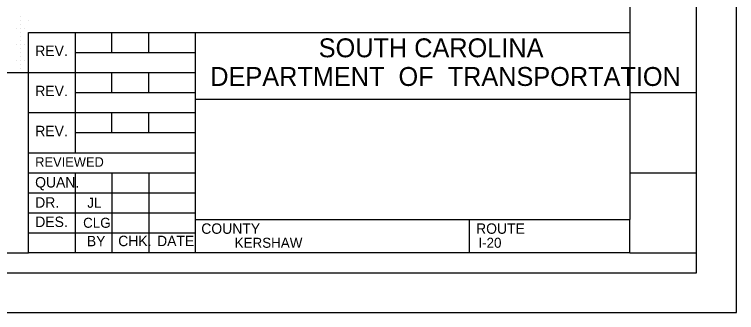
# Model space of a CAD drawing. Extents: x -1.4 to 34.6, y 0.5 to 22.5.
# Drawn here: x 25.59 to 34.6, y 0.5 to 4.22 of the extents above; entities that cross this region are included whole.
import ezdxf

# ---------------------------------------------------------------- set-up
doc = ezdxf.new("R2010")
doc.units = 0
for name, color, linetype in [('BR_BORDER LINES', 7, 'Continuous'), ('BR_GRID DOTS', 7, 'Continuous'), ('BR_GRID LINES', 7, 'Continuous'), ('BR_TEXT', 7, 'Continuous'), ('RD_SHT_IplotShp', 7, 'Continuous')]:
    doc.layers.add(name, color=color, linetype=linetype)

msp = doc.modelspace()

# ---------------------------------------------------------------- linework, layer by layer
at = {"layer": 'BR_BORDER LINES'}
for p, q in [((34.097, 0.993), (34.097, 21.9962)), ((33.2637, 11.2429), (33.2637, 4.043)), ((25.7637, 1.243), (25.7637, 3.993)), ((25.7637, 3.993), (33.2637, 3.993)), ((26.347, 3.993), (26.347, 2.493)), ((26.8054, 3.743), (26.8054, 3.993)), ((27.2637, 3.743), (27.2637, 3.993)), ((27.847, 1.243), (27.847, 3.993)), ((33.2637, 4.043), (33.2637, 1.6597)), ((26.347, 3.743), (27.847, 3.743)), ((23.4512, 3.493), (25.7637, 3.493)), ((25.7637, 3.493), (27.847, 3.493)), ((26.8054, 3.243), (26.8054, 3.493)), ((27.2637, 3.243), (27.2637, 3.493)), ((26.347, 3.243), (27.847, 3.243)), ((27.847, 3.1597), (33.2637, 3.1597)), ((27.847, 3.1597), (27.847, 3.1597)), ((33.2637, 3.1597), (33.2637, 3.1597)), ((25.7637, 2.993), (27.847, 2.993)), ((26.8054, 2.743), (26.8054, 2.993)), ((27.2637, 2.743), (27.2637, 2.993)), ((26.347, 2.743), (27.847, 2.743)), ((25.7637, 2.493), (27.847, 2.493)), ((25.7637, 2.243), (27.847, 2.243)), ((26.347, 2.243), (26.347, 1.243)), ((26.8054, 2.243), (26.8054, 1.243)), ((27.2637, 2.243), (27.2637, 1.243)), ((25.7637, 1.993), (27.847, 1.993)), ((25.7637, 1.743), (27.847, 1.743)), ((27.847, 1.6597), (33.2637, 1.6597)), ((31.2637, 1.243), (31.2637, 1.6597)), ((33.2637, 1.243), (33.2637, 1.6597)), ((25.7637, 1.493), (27.847, 1.493)), ((1.264, 1.243), (25.7638, 1.243)), ((33.2637, 1.243), (25.7638, 1.243)), ((0.4307, 0.993), (34.097, 0.993))]:
    msp.add_line(p, q, dxfattribs=at)
at = {"layer": 'BR_GRID DOTS'}
for p, q in [((25.6638, 4.193), (25.6638, 4.193)), ((25.6638, 4.143), (25.6638, 4.143)), ((25.6638, 4.093), (25.6638, 4.093)), ((25.6638, 4.093), (25.6638, 4.093)), ((25.7638, 4.143), (25.7638, 4.143)), ((25.6138, 4.043), (25.6138, 4.043)), ((25.6638, 4.043), (25.6638, 4.043)), ((25.6638, 3.993), (25.6638, 3.993)), ((25.7138, 4.043), (25.7138, 4.043)), ((25.6638, 3.943), (25.6638, 3.943)), ((25.6638, 3.893), (25.6638, 3.893)), ((25.6138, 3.843), (25.6138, 3.843)), ((25.6638, 3.843), (25.6638, 3.843)), ((25.6638, 3.793), (25.6638, 3.793)), ((25.7138, 3.843), (25.7138, 3.843)), ((25.6638, 3.743), (25.6638, 3.743)), ((25.6138, 3.643), (25.6138, 3.643)), ((25.6638, 3.693), (25.6638, 3.693)), ((25.6638, 3.643), (25.6638, 3.643)), ((25.7138, 3.643), (25.7138, 3.643)), ((25.6638, 3.593), (25.6638, 3.593)), ((25.6638, 3.543), (25.6638, 3.543))]:
    msp.add_line(p, q, dxfattribs=at)
at = {"layer": 'BR_GRID LINES'}
for p, q in [((33.2637, 3.243), (34.097, 3.243)), ((33.2637, 2.243), (34.097, 2.243)), ((33.2637, 1.243), (34.097, 1.243))]:
    msp.add_line(p, q, dxfattribs=at)
at = {"layer": 'RD_SHT_IplotShp'}
msp.add_lwpolyline([(-1.403, 0.4978), (34.597, 0.4978), (34.597, 22.4978), (-1.403, 22.4978)], close=True, dxfattribs=at)

# ---------------------------------------------------------------- texts
at = {"layer": 'BR_TEXT'}
for s, height, p in [('SOUTH CAROLINA', 0.235852, (29.3844, 3.6835)), ('REV.', 0.13, (25.8484, 3.6984)), ('DEPARTMENT  OF  TRANSPORTATION', 0.235852, (28.0318, 3.3258)), ('REV.', 0.13, (25.8484, 3.1984)), ('REV.', 0.13, (25.8484, 2.6984)), ('REVIEWED', 0.12, (25.8477, 2.3165)), ('QUAN.', 0.13, (25.8471, 2.0582)), ('DR.', 0.13, (25.8473, 1.8067)), ('JL', 0.125, (26.4975, 1.8055)), ('DES.', 0.13, (25.8484, 1.5654)), ('CLG', 0.125, (26.4455, 1.5555)), ('COUNTY', 0.13, (27.9195, 1.4805)), ('ROUTE', 0.13, (31.3477, 1.4805)), ('BY', 0.13, (26.4924, 1.325)), ('CHK.', 0.13, (26.8832, 1.3264)), ('DATE', 0.13, (27.3684, 1.3265)), ('KERSHAW        ', 0.125, (28.3359, 1.3061)), ('I-20', 0.125, (31.3762, 1.3061))]:
    msp.add_text(s, height=height, dxfattribs=at).set_placement(p)

doc.saveas('drawing.dxf')
